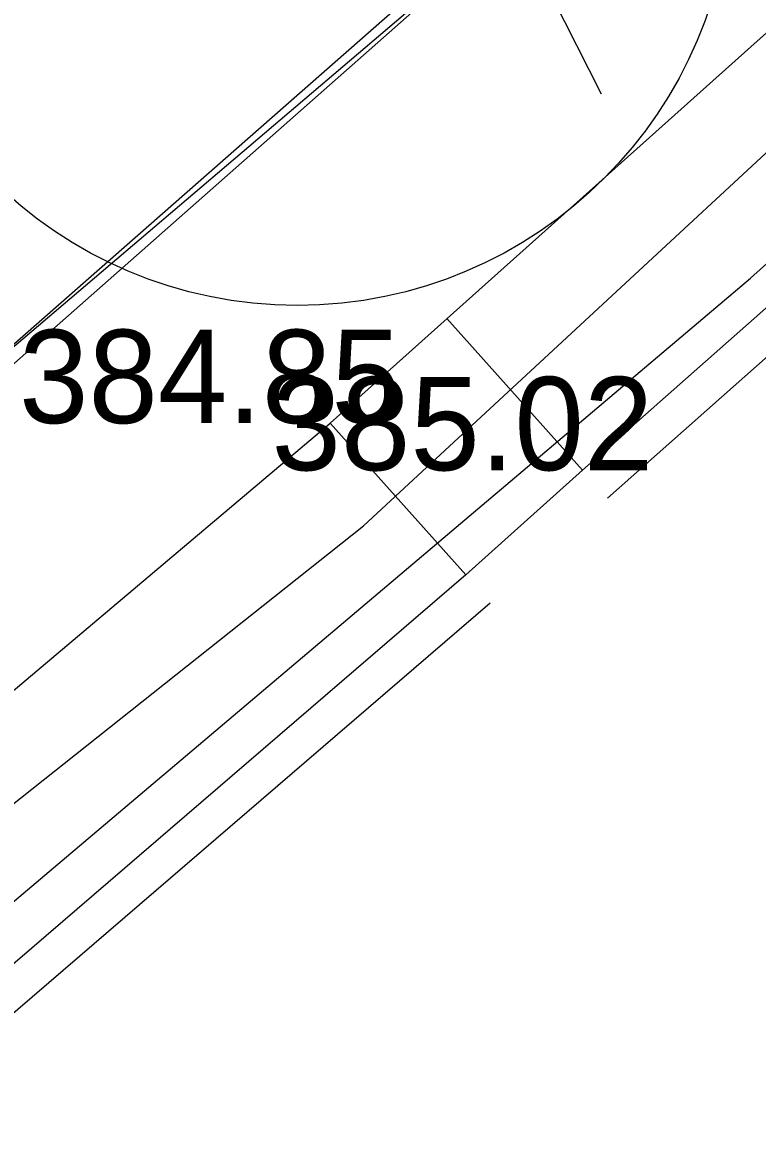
# Model space of a CAD drawing. Extents: x -438233 to -437334, y -1133133 to -1132623.
# Drawn here: x -438079.61 to -438073.71, y -1133022.09 to -1133013.03 of the extents above; entities that cross this region are included whole.
import ezdxf

# ---------------------------------------------------------------- set-up
doc = ezdxf.new("R2010")
doc.units = 0
for name, color, linetype in [('Vrstva 1', 7, 'Continuous'), ('Vrstva 11', 7, 'Continuous'), ('Vrstva 3', 7, 'Continuous'), ('Vrstva 40', 7, 'Continuous'), ('Vrstva 53', 7, 'Continuous'), ('Vrstva 55', 7, 'Continuous'), ('Vrstva 7', 7, 'Continuous'), ('Vrstva 8', 7, 'Continuous')]:
    doc.layers.add(name, color=color, linetype=linetype)

msp = doc.modelspace()

# ---------------------------------------------------------------- linework, layer by layer
at = {"layer": 'Vrstva 1'}
for p, q in [((-438077.139, -1133016.254), (-438077.139, -1133016.254)), ((-438075.11, -1133016.633), (-438075.11, -1133016.633))]:
    msp.add_line(p, q, dxfattribs=at)
at = {"layer": 'Vrstva 11'}
for p, q in [((-438076.201, -1133015.414), (-438075.11, -1133016.633)), ((-438077.139, -1133016.254), (-438076.048, -1133017.473))]:
    msp.add_line(p, q, dxfattribs=at)
for points in [[(-438079.851, -1133001.541), (-438081.143, -1133003.836), (-438082.651, -1133014.98), (-438080.295, -1133016.157), (-438070.78, -1133008.056), (-438059.123, -1132997.555), (-438044.087, -1132984.346), (-438028.394, -1132970.577), (-438016.298, -1132960.009), (-438006.567, -1132951.363)], [(-438080.927, -1133019.451), (-438077.139, -1133016.254), (-438069.364, -1133009.292), (-438057.759, -1132998.987), (-438043.045, -1132985.96), (-438027.231, -1132972.034), (-438013.435, -1132960.019)]]:
    msp.add_lwpolyline(points, dxfattribs=at)
at = {"layer": 'Vrstva 40'}
msp.add_lwpolyline([(-438006.5668, -1132951.3629), (-438080.295, -1133016.157), (-438085.2072, -1133012.0709), (-438080.5464, -1133006.8034), (-438077.1818, -1133006.2314), (-438076.5557, -1133006.7587), (-438075.9136, -1133005.9921), (-438066.4017, -1132994.506), (-438073.0336, -1132988.8171), (-438072.3528, -1132988.0234), (-438069.6652, -1132990.252), (-438068.2866, -1132988.6064), (-438065.6037, -1132990.8541), (-438063.7995, -1132988.7005), (-438061.1166, -1132990.9482), (-438050.7956, -1132978.6286), (-438047.7203, -1132977.5896), (-438045.2045, -1132976.3935), (-438042.6778, -1132974.8844), (-438040.928, -1132973.6336), (-438039.5901, -1132972.5144), (-438037.876, -1132970.8704), (-438035.3972, -1132967.8064), (-438020.0066, -1132954.1238)], dxfattribs=at)
msp.add_circle((-438077.4031, -1133011.8187), 3.4889, dxfattribs=at)
at = {"layer": 'Vrstva 53'}
for points in [[(-438082.34, -1133022.27), (-438082.4, -1133022.17), (-438081.23, -1133020.54), (-438076.87, -1133017.08), (-438069.83, -1133010.55), (-438064.49, -1133005.53), (-438059.58, -1133001.78), (-438053.45, -1132996.74), (-438044, -1132988.47), (-438035.57, -1132981.06), (-438029.47, -1132975.65), (-438020.01, -1132967.31), (-438013.46, -1132961.68), (-438012.29, -1132959.83), (-438009.79, -1132957.66), (-438009.76, -1132957.6), (-438007.47, -1132956.33), (-438007.65, -1132955.49), (-438008.56, -1132952.65)], [(-438080.2279, -1133025.0897), (-438082.04, -1133022.81), (-438081.87, -1133021.95), (-438073.76, -1133015.09), (-438028.25, -1132974.2), (-438011.87, -1132960.69), (-438014.77, -1132957.4)]]:
    msp.add_lwpolyline(points, dxfattribs=at)
at = {"layer": 'Vrstva 55'}
for points in [[(-438074.9586, -1133013.6101), (-438076.856, -1133009.846), (-438083.298, -1132998.719), (-438115.192, -1132972.054), (-438146.469, -1132953.711), (-438176.9, -1132931.48)], [(-437979.8206, -1132940.7597), (-437988.363, -1132937.437), (-438041.643, -1132982.184), (-438086.6359, -1133021.9185)]]:
    msp.add_lwpolyline(points, dxfattribs=at)
at = {"layer": 'Vrstva 7'}
for points in [[(-438075.11, -1133016.633), (-438066.939, -1133009.393), (-438057.287, -1133000.946), (-438041.953, -1132987.39), (-438025.485, -1132972.915), (-438016.315, -1132964.831), (-438000.869, -1132951.177), (-437989.371, -1132943.616), (-437973.864, -1132938.609), (-437972.7422, -1132939.0477)], [(-438074.911, -1133016.858), (-438066.741, -1133009.618), (-438057.089, -1133001.171), (-438041.755, -1132987.615), (-438025.287, -1132973.14), (-438016.116, -1132965.056), (-438000.686, -1132951.416), (-437989.24, -1132943.889), (-437973.874, -1132938.927), (-437973.0529, -1132939.2481)], [(-438076.048, -1133017.473), (-438081.667, -1133022.306), (-438080.2019, -1133023.9892)], [(-438080.4352, -1133023.2649), (-438081.243, -1133022.337), (-438075.852, -1133017.7)]]:
    msp.add_lwpolyline(points, dxfattribs=at)
at = {"layer": 'Vrstva 8'}
msp.add_line((-438075.11, -1133016.633), (-438076.048, -1133017.473), dxfattribs=at)

# ---------------------------------------------------------------- texts
at = {"layer": 'Vrstva 3'}
for s, p in [('384.85 ', (-438079.639, -1133016.254)), ('385.02 ', (-438077.61, -1133016.633))]:
    msp.add_text(s, height=0.75, dxfattribs=at).set_placement(p)

doc.saveas('drawing.dxf')
